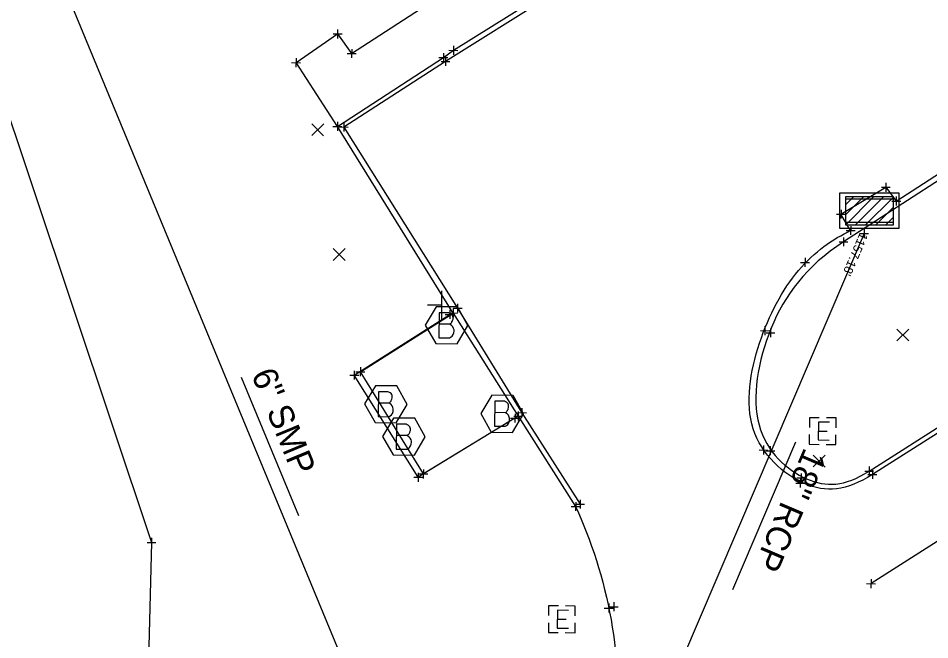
# Model space of a CAD drawing. Extents: x 142461 to 147261, y 511126 to 514697.
# Drawn here: x 145178.7 to 145281.3, y 513623.9 to 513693.8 of the extents above; entities that cross this region are included whole.
import ezdxf

# ---------------------------------------------------------------- set-up
doc = ezdxf.new("R2010")
doc.units = 0
for name, color, linetype in [('DR_X_Cells', 7, 'Continuous'), ('DR_X_Elev_Flow', 7, 'Continuous'), ('DR_X_Storm_Sewer', 7, 'Continuous'), ('DR_X_Text', 7, 'Continuous'), ('GK_Drainage_Nodes', 7, 'Continuous'), ('PM_X_Surveyed_Line', 7, 'Continuous'), ('PV_X_Curb', 7, 'Continuous'), ('PV_X_EOP', 7, 'Continuous'), ('PV_X_Walk', 7, 'Continuous'), ('RD_X_Cells', 7, 'Continuous'), ('RD_X_Concrete_Pad', 7, 'Continuous'), ('RD_X_Fence', 7, 'Continuous'), ('SC_Scratch1', 7, 'Continuous'), ('SN_X_Public', 7, 'Continuous'), ('SV_X_Random_Point', 7, 'Continuous'), ('SV_X_Shot_Marker', 7, 'Continuous'), ('UT_X_Electric_Cells', 7, 'Continuous'), ('UT_X_Sanitary_Line', 7, 'Continuous'), ('UT_X_Sanitary_Text', 7, 'Continuous'), ('VG_X_Tree_Line_Lt', 7, 'Continuous')]:
    doc.layers.add(name, color=color, linetype=linetype)

msp = doc.modelspace()

# ---------------------------------------------------------------- linework, layer by layer
at = {"layer": 'DR_X_Cells'}
for p, q in [((145271.86, 513670.59), (145275.04, 513673.77)), ((145271.86, 513671.72), (145273.91, 513673.77)), ((145271.86, 513672.85), (145272.78, 513673.77)), ((145272.94, 513670.54), (145276.17, 513673.77)), ((145274.07, 513670.54), (145277.19, 513673.66)), ((145275.2, 513670.54), (145277.19, 513672.53)), ((145276.33, 513670.54), (145277.19, 513671.4))]:
    msp.add_line(p, q, dxfattribs=at)
for points in [[(145271.19, 513674.16), (145277.86, 513674.16), (145277.86, 513670.16), (145271.19, 513670.16)], [(145271.86, 513673.77), (145277.19, 513673.77), (145277.19, 513670.54), (145271.86, 513670.54)], [(145271.86, 513673.49), (145277.19, 513673.49), (145277.19, 513670.83), (145271.86, 513670.83)]]:
    msp.add_lwpolyline(points, close=True, dxfattribs=at)
at = {"layer": 'DR_X_Elev_Flow'}
for p, q in [((145273.93, 513670.08), (145273.93, 513669.08)), ((145273.43, 513669.58), (145274.43, 513669.58)), ((145273.93, 513669.58), (145273.93, 513669.58))]:
    msp.add_line(p, q, dxfattribs=at)
at = {"layer": 'DR_X_Storm_Sewer'}
msp.add_line((145273.93, 513669.58), (145249.1, 513611.47), dxfattribs=at)
at = {"layer": 'DR_X_Text'}
for p, q in [((145210.32, 513637.82), (145203.87, 513653.41)), ((145259.16, 513629.54), (145266.26, 513646.14)), ((145259.16, 513629.54), (145266.26, 513646.14))]:
    msp.add_line(p, q, dxfattribs=at)
at = {"layer": 'GK_Drainage_Nodes'}
for p, q in [((145274.52, 513674.16), (145274.52, 513674.16)), ((145274.52, 513673.49), (145274.52, 513673.49)), ((145271.86, 513672.16), (145271.86, 513672.16)), ((145274.52, 513672.16), (145274.52, 513672.16)), ((145274.52, 513672.16), (145274.52, 513672.16)), ((145277.19, 513672.16), (145277.19, 513672.16)), ((145274.52, 513670.83), (145274.52, 513670.83)), ((145274.52, 513670.54), (145274.52, 513670.54)), ((145274.52, 513670.16), (145274.52, 513670.16))]:
    msp.add_line(p, q, dxfattribs=at)
at = {"layer": 'PM_X_Surveyed_Line'}
msp.add_lwpolyline([(145586.02, 513828.49), (145510.32, 513779.96), (145430.23, 513729.01), (145345.65, 513675.34), (145274.72, 513630.19)], dxfattribs=at)
at = {"layer": 'PV_X_Curb'}
for p, q in [((145293.56, 513682.87), (145271.62, 513668.66)), ((145274.5, 513642.86), (145306.01, 513662.87)), ((145235, 513649.05), (145241.47, 513638.88))]:
    msp.add_line(p, q, dxfattribs=at)
msp.add_lwpolyline([(145227.69, 513660.65), (145214.65, 513681.65), (145226.59, 513689.4), (145227.71, 513690.22), (145253.7, 513706.45), (145254.76, 513707.01), (145306.51, 513740.01), (145357, 513772.11), (145410.28, 513806.15), (145439.46, 513824.75), (145448.27, 513830.42), (145452.54, 513833.13), (145456.82, 513835.85), (145503.2, 513865.44), (145542.33, 513890.92), (145551.43, 513885.04), (145559.02, 513886.59), (145559.54, 513886.77)], dxfattribs=at)
for points in [[(145271.62, 513668.66), (145267.39, 513665.92), (145262.61, 513659.37), (145260.63, 513647), (145267.57, 513640.94), (145271.73, 513641.1), (145274.5, 513642.86)], [(145241.47, 513638.88), (145243.17, 513635.15), (145246.14, 513626.19), (145246.47, 513612.52), (145244.7, 513603.43), (145243.59, 513599.69)]]:
    msp.add_open_spline(points, degree=3, dxfattribs=at)
at = {"layer": 'PV_X_EOP'}
for p, q in [((145255.01, 513706.63), (145226.82, 513688.97)), ((145226.82, 513688.97), (145215.37, 513681.58)), ((145277.55, 513673.25), (145293.23, 513683.36)), ((145215.37, 513681.58), (145228.18, 513661.2)), ((145271.33, 513671.77), (145276.38, 513674.8)), ((145276.38, 513674.8), (145277.55, 513673.25)), ((145272.42, 513669.94), (145271.33, 513671.77)), ((145272.42, 513669.94), (145272.42, 513669.94)), ((145306.3, 513662.46), (145274.87, 513642.48)), ((145228.18, 513661.2), (145235.42, 513649.43)), ((145235.42, 513649.43), (145241.98, 513639.13))]:
    msp.add_line(p, q, dxfattribs=at)
msp.add_open_spline([(145274.87, 513642.48), (145271.92, 513640.6), (145267.32, 513640.24), (145259.92, 513646.95), (145261.72, 513657.62), (145266.25, 513666.12), (145270.44, 513668.98), (145272.42, 513669.94)], degree=3, dxfattribs=at)
at = {"layer": 'PV_X_Walk'}
for p, q in [((145216.26, 513689.85), (145225.94, 513696.17)), ((145210, 513688.83), (145214.68, 513692.05)), ((145214.68, 513692.05), (145216.26, 513689.85)), ((145214.65, 513681.65), (145210, 513688.83))]:
    msp.add_line(p, q, dxfattribs=at)
at = {"layer": 'RD_X_Cells'}
for p, q in [((145225.77, 513661.35), (145224.54, 513659.29)), ((145228.17, 513661.33), (145225.77, 513661.35)), ((145229.34, 513659.24), (145228.17, 513661.33)), ((145224.54, 513659.29), (145225.72, 513657.2)), ((145228.12, 513657.17), (145229.34, 513659.24)), ((145225.72, 513657.2), (145228.12, 513657.17)), ((145218.93, 513652.47), (145217.71, 513650.41)), ((145221.33, 513652.45), (145218.93, 513652.47)), ((145222.51, 513650.36), (145221.33, 513652.45)), ((145232.02, 513651.4), (145230.8, 513649.34)), ((145234.42, 513651.38), (145232.02, 513651.4)), ((145235.6, 513649.29), (145234.42, 513651.38)), ((145217.71, 513650.41), (145218.89, 513648.32)), ((145221.28, 513648.29), (145222.51, 513650.36)), ((145230.8, 513649.34), (145231.98, 513647.24)), ((145234.38, 513647.22), (145235.6, 513649.29)), ((145218.89, 513648.32), (145221.28, 513648.29)), ((145220.97, 513648.82), (145219.75, 513646.76)), ((145223.37, 513648.8), (145220.97, 513648.82)), ((145224.55, 513646.71), (145223.37, 513648.8)), ((145231.98, 513647.24), (145234.38, 513647.22)), ((145219.75, 513646.76), (145220.92, 513644.67)), ((145223.32, 513644.64), (145224.55, 513646.71)), ((145220.92, 513644.67), (145223.32, 513644.64))]:
    msp.add_line(p, q, dxfattribs=at)
for points in [[(145227.31, 513659.38), (145227.42, 513659.49), (145227.49, 513659.56), (145227.53, 513659.62), (145227.55, 513659.67), (145227.6, 513659.75), (145227.62, 513659.82), (145227.67, 513659.97), (145227.67, 513660.04), (145227.67, 513660.13), (145227.65, 513660.26), (145227.61, 513660.37), (145227.54, 513660.46), (145227.43, 513660.55), (145227.34, 513660.59), (145227.3, 513660.62), (145227.19, 513660.66), (145226.11, 513660.67), (145226.08, 513657.87), (145227.29, 513657.86), (145227.45, 513657.95), (145227.58, 513658.06), (145227.69, 513658.23), (145227.76, 513658.43), (145227.79, 513658.63), (145227.79, 513658.76), (145227.74, 513658.89), (145227.66, 513659.09), (145227.55, 513659.22), (145227.31, 513659.38), (145226.1, 513659.39)], [(145220.47, 513650.5), (145220.58, 513650.61), (145220.65, 513650.68), (145220.69, 513650.74), (145220.72, 513650.79), (145220.76, 513650.87), (145220.78, 513650.94), (145220.83, 513651.09), (145220.83, 513651.16), (145220.83, 513651.25), (145220.81, 513651.38), (145220.77, 513651.49), (145220.7, 513651.58), (145220.59, 513651.67), (145220.51, 513651.71), (145220.46, 513651.74), (145220.35, 513651.78), (145219.27, 513651.79), (145219.24, 513648.99), (145220.46, 513648.98), (145220.61, 513649.07), (145220.74, 513649.18), (145220.86, 513649.35), (145220.92, 513649.55), (145220.95, 513649.75), (145220.95, 513649.88), (145220.91, 513650.01), (145220.82, 513650.21), (145220.71, 513650.34), (145220.47, 513650.5), (145219.26, 513650.51)], [(145233.57, 513649.43), (145233.68, 513649.54), (145233.74, 513649.6), (145233.79, 513649.67), (145233.81, 513649.71), (145233.86, 513649.8), (145233.88, 513649.87), (145233.92, 513650.02), (145233.92, 513650.09), (145233.93, 513650.17), (145233.91, 513650.31), (145233.86, 513650.42), (145233.8, 513650.51), (145233.69, 513650.6), (145233.6, 513650.64), (145233.56, 513650.66), (145233.45, 513650.71), (145232.37, 513650.72), (145232.34, 513647.92), (145233.55, 513647.91), (145233.7, 513647.99), (145233.84, 513648.1), (145233.95, 513648.28), (145234.02, 513648.48), (145234.04, 513648.67), (145234.04, 513648.81), (145234, 513648.94), (145233.92, 513649.14), (145233.81, 513649.27), (145233.57, 513649.43), (145232.35, 513649.44)], [(145222.51, 513646.85), (145222.62, 513646.96), (145222.69, 513647.02), (145222.73, 513647.09), (145222.76, 513647.13), (145222.8, 513647.22), (145222.82, 513647.29), (145222.87, 513647.44), (145222.87, 513647.51), (145222.87, 513647.6), (145222.85, 513647.73), (145222.81, 513647.84), (145222.74, 513647.93), (145222.63, 513648.02), (145222.55, 513648.06), (145222.5, 513648.08), (145222.39, 513648.13), (145221.31, 513648.14), (145221.28, 513645.34), (145222.5, 513645.33), (145222.65, 513645.42), (145222.78, 513645.52), (145222.9, 513645.7), (145222.96, 513645.9), (145222.99, 513646.1), (145222.99, 513646.23), (145222.95, 513646.36), (145222.86, 513646.56), (145222.75, 513646.69), (145222.51, 513646.85), (145221.3, 513646.86)]]:
    msp.add_lwpolyline(points, dxfattribs=at)
at = {"layer": 'RD_X_Concrete_Pad'}
msp.add_lwpolyline([(145217.24, 513654.04), (145227.69, 513660.65), (145235, 513649.05), (145224.33, 513642.54)], close=True, dxfattribs=at)
at = {"layer": 'RD_X_Fence'}
msp.add_lwpolyline([(145234.64, 513648.82), (145223.76, 513642.16), (145216.55, 513653.65), (145227.3, 513660.49)], dxfattribs=at)
at = {"layer": 'SN_X_Public'}
for p, q in [((145226.39, 513663.13), (145226.39, 513659.93)), ((145226.39, 513661.53), (145224.79, 513661.53)), ((145226.39, 513661.53), (145226.39, 513661.53))]:
    msp.add_line(p, q, dxfattribs=at)
at = {"layer": 'SV_X_Random_Point'}
for p, q in [((145211.78, 513680.61), (145213.13, 513681.93)), ((145211.79, 513681.95), (145213.11, 513680.6)), ((145214.18, 513666.56), (145215.52, 513667.9)), ((145214.18, 513667.9), (145215.52, 513666.56)), ((145277.62, 513657.5), (145278.95, 513658.84)), ((145277.62, 513658.84), (145278.95, 513657.5)), ((145268.2, 513643.32), (145269.55, 513644.64)), ((145268.22, 513644.66), (145269.54, 513643.31))]:
    msp.add_line(p, q, dxfattribs=at)
at = {"layer": 'SV_X_Shot_Marker'}
for p, q in [((145214.68, 513692.55), (145214.67, 513691.55)), ((145214.18, 513692.06), (145215.18, 513692.05)), ((145214.68, 513692.05), (145214.68, 513692.05)), ((145216.27, 513690.35), (145216.26, 513689.35)), ((145227.21, 513690.22), (145228.21, 513690.21)), ((145227.72, 513690.72), (145227.71, 513689.72)), ((145227.71, 513690.22), (145227.71, 513690.22)), ((145210, 513689.33), (145209.99, 513688.33)), ((145215.76, 513689.85), (145216.76, 513689.84)), ((145216.26, 513689.85), (145216.26, 513689.85)), ((145226.09, 513689.4), (145227.09, 513689.39)), ((145226.59, 513689.9), (145226.58, 513688.9)), ((145226.59, 513689.4), (145226.59, 513689.4)), ((145226.83, 513689.47), (145226.82, 513688.47)), ((145209.5, 513688.83), (145210.5, 513688.82)), ((145210, 513688.83), (145210, 513688.83)), ((145226.32, 513688.97), (145227.32, 513688.96)), ((145226.82, 513688.97), (145226.82, 513688.97)), ((145214.66, 513682.15), (145214.65, 513681.15)), ((145214.66, 513682.15), (145214.65, 513681.15)), ((145215.38, 513682.08), (145215.37, 513681.08)), ((145214.15, 513681.65), (145215.15, 513681.64)), ((145214.15, 513681.65), (145215.15, 513681.64)), ((145214.65, 513681.65), (145214.65, 513681.65)), ((145214.65, 513681.65), (145214.65, 513681.65)), ((145214.87, 513681.59), (145215.87, 513681.58)), ((145215.37, 513681.58), (145215.37, 513681.58)), ((145275.88, 513674.81), (145276.88, 513674.8)), ((145276.38, 513675.3), (145276.37, 513674.3)), ((145276.38, 513674.8), (145276.38, 513674.8)), ((145277.05, 513673.25), (145278.05, 513673.24)), ((145277.56, 513673.75), (145277.55, 513672.75)), ((145277.55, 513673.25), (145277.55, 513673.25)), ((145270.83, 513671.77), (145271.83, 513671.76)), ((145271.34, 513672.27), (145271.33, 513671.27)), ((145271.33, 513671.77), (145271.33, 513671.77)), ((145271.92, 513669.94), (145272.92, 513669.93)), ((145272.43, 513670.44), (145272.42, 513669.44)), ((145272.42, 513669.94), (145272.42, 513669.94)), ((145271.12, 513668.67), (145272.12, 513668.66)), ((145271.63, 513669.16), (145271.61, 513668.16)), ((145271.62, 513668.66), (145271.62, 513668.66)), ((145267.29, 513666.84), (145267.28, 513665.84)), ((145266.78, 513666.34), (145267.78, 513666.33)), ((145267.28, 513666.34), (145267.28, 513666.34)), ((145228.19, 513661.7), (145228.18, 513660.7)), ((145226.8, 513660.49), (145227.8, 513660.48)), ((145227.19, 513660.66), (145228.19, 513660.65)), ((145227.19, 513660.66), (145228.19, 513660.65)), ((145227.31, 513660.99), (145227.3, 513659.99)), ((145227.3, 513660.49), (145227.3, 513660.49)), ((145227.68, 513661.21), (145228.68, 513661.2)), ((145227.69, 513661.15), (145227.68, 513660.15)), ((145227.69, 513661.15), (145227.68, 513660.15)), ((145227.69, 513660.65), (145227.69, 513660.65)), ((145227.69, 513660.65), (145227.69, 513660.65)), ((145228.18, 513661.2), (145228.18, 513661.2)), ((145262.27, 513658.67), (145263.27, 513658.66)), ((145262.77, 513659.16), (145262.76, 513658.16)), ((145262.77, 513658.66), (145262.77, 513658.66)), ((145262.9, 513658.42), (145263.9, 513658.41)), ((145263.41, 513658.92), (145263.4, 513657.92)), ((145263.4, 513658.42), (145263.4, 513658.42)), ((145217.24, 513654.54), (145217.23, 513653.54)), ((145216.05, 513653.65), (145217.05, 513653.64)), ((145216.55, 513654.15), (145216.54, 513653.15)), ((145216.55, 513653.65), (145216.55, 513653.65)), ((145216.74, 513654.04), (145217.74, 513654.03)), ((145217.24, 513654.04), (145217.24, 513654.04)), ((145234.65, 513649.32), (145234.64, 513648.32)), ((145234.92, 513649.44), (145235.92, 513649.42)), ((145235.01, 513649.55), (145235, 513648.55)), ((145235.01, 513649.55), (145235, 513648.55)), ((145235.42, 513649.93), (145235.41, 513648.93)), ((145235.42, 513649.43), (145235.42, 513649.43)), ((145234.14, 513648.83), (145235.14, 513648.82)), ((145234.5, 513649.05), (145235.5, 513649.04)), ((145234.5, 513649.05), (145235.5, 513649.04)), ((145234.64, 513648.82), (145234.64, 513648.82)), ((145235, 513649.05), (145235, 513649.05)), ((145235, 513649.05), (145235, 513649.05)), ((145262.11, 513645.24), (145263.11, 513645.23)), ((145262.61, 513645.73), (145262.6, 513644.73)), ((145262.61, 513645.23), (145262.61, 513645.23)), ((145262.88, 513645.15), (145263.88, 513645.14)), ((145263.38, 513645.65), (145263.37, 513644.65)), ((145263.38, 513645.15), (145263.38, 513645.15)), ((145224.33, 513643.04), (145224.32, 513642.04)), ((145274.5, 513643.36), (145274.49, 513642.36)), ((145274.88, 513642.98), (145274.87, 513641.98)), ((145223.26, 513642.17), (145224.26, 513642.16)), ((145223.76, 513642.66), (145223.75, 513641.66)), ((145223.76, 513642.16), (145223.76, 513642.16)), ((145223.83, 513642.55), (145224.83, 513642.54)), ((145224.33, 513642.54), (145224.33, 513642.54)), ((145266.36, 513642.1), (145267.36, 513642.09)), ((145266.76, 513642), (145266.75, 513641)), ((145266.86, 513642.6), (145266.85, 513641.6)), ((145266.86, 513642.1), (145266.86, 513642.1)), ((145274, 513642.86), (145275, 513642.85)), ((145274.37, 513642.49), (145275.37, 513642.48)), ((145274.5, 513642.86), (145274.5, 513642.86)), ((145274.87, 513642.48), (145274.87, 513642.48)), ((145266.25, 513641.5), (145267.25, 513641.49)), ((145266.75, 513641.5), (145266.75, 513641.5)), ((145240.97, 513638.89), (145241.97, 513638.88)), ((145241.48, 513639.38), (145241.47, 513638.38)), ((145241.47, 513638.88), (145241.47, 513638.88)), ((145241.48, 513639.13), (145242.48, 513639.12)), ((145241.99, 513639.63), (145241.98, 513638.63)), ((145241.98, 513639.13), (145241.98, 513639.13)), ((145193.23, 513634.84), (145194.23, 513634.84)), ((145193.73, 513635.34), (145193.73, 513634.34)), ((145193.73, 513634.84), (145193.73, 513634.84)), ((145274.72, 513630.69), (145274.71, 513629.69)), ((145274.22, 513630.19), (145275.22, 513630.18)), ((145274.72, 513630.19), (145274.72, 513630.19)), ((145245.2, 513627.95), (145245.19, 513626.95)), ((145245.26, 513627.59), (145246.26, 513627.58)), ((145245.76, 513628.09), (145245.75, 513627.09)), ((145244.69, 513627.45), (145245.69, 513627.44)), ((145245.19, 513627.45), (145245.19, 513627.45)), ((145245.76, 513627.59), (145245.76, 513627.59))]:
    msp.add_line(p, q, dxfattribs=at)
at = {"layer": 'UT_X_Electric_Cells'}
for p, q in [((145268.78, 513647.36), (145269.78, 513647.35)), ((145269.28, 513647.36), (145269.28, 513647.36)), ((145239.41, 513626.19), (145240.41, 513626.18)), ((145239.91, 513626.19), (145239.91, 513626.19))]:
    msp.add_line(p, q, dxfattribs=at)
for points in [[(145268.89, 513648.86), (145267.79, 513648.87), (145267.78, 513647.77)], [(145270.04, 513648.35), (145268.79, 513648.36), (145268.77, 513646.36), (145270.02, 513646.35)], [(145270.78, 513647.74), (145270.79, 513648.84), (145269.69, 513648.85)], [(145267.77, 513646.97), (145267.76, 513645.87), (145268.86, 513645.86)], [(145269.66, 513645.85), (145270.76, 513645.84), (145270.77, 513646.94)], [(145239.53, 513627.69), (145238.43, 513627.7), (145238.41, 513626.6)], [(145241.41, 513626.57), (145241.43, 513627.67), (145240.33, 513627.68)], [(145240.67, 513627.18), (145239.42, 513627.19), (145239.4, 513625.19), (145240.65, 513625.18)], [(145238.41, 513625.8), (145238.4, 513624.7), (145239.5, 513624.69)], [(145240.3, 513624.68), (145241.4, 513624.67), (145241.41, 513625.77)]]:
    msp.add_lwpolyline(points, dxfattribs=at)
at = {"layer": 'UT_X_Sanitary_Line'}
msp.add_line((145182.95, 513699.65), (145226.66, 513594.02), dxfattribs=at)
at = {"layer": 'UT_X_Sanitary_Text'}
msp.add_line((145210.32, 513637.82), (145203.87, 513653.41), dxfattribs=at)
at = {"layer": 'VG_X_Tree_Line_Lt'}
msp.add_lwpolyline([(145264.43, 514020.19), (145272.43, 513964.36), (145272.27, 513933.74), (145243.1, 513916.38), (145224, 513919.89), (145186.54, 513901.3), (145152.02, 513842.38), (145120.24, 513791.81), (145167.13, 513714.33), (145193.73, 513634.84), (145192.23, 513576.23)], dxfattribs=at)

# ---------------------------------------------------------------- texts
at = {"layer": 'DR_X_Text'}
for s, rotation, p in [('6" SMP', 292.4779, (145204.93, 513653.73)), ('18" RCP', 246.8585, (145267.22, 513645.6))]:
    msp.add_text(s, height=2.8, rotation=rotation, dxfattribs=at).set_placement(p)
at = {"layer": 'SC_Scratch1'}
msp.add_text("1157.18'", height=1, rotation=246.8585, dxfattribs=at).set_placement((145273.48, 513669.78))
at = {"layer": 'UT_X_Sanitary_Text'}
msp.add_text('6" SMP', height=2.8, rotation=292.4779, dxfattribs=at).set_placement((145204.93, 513653.73))

doc.saveas('drawing.dxf')
